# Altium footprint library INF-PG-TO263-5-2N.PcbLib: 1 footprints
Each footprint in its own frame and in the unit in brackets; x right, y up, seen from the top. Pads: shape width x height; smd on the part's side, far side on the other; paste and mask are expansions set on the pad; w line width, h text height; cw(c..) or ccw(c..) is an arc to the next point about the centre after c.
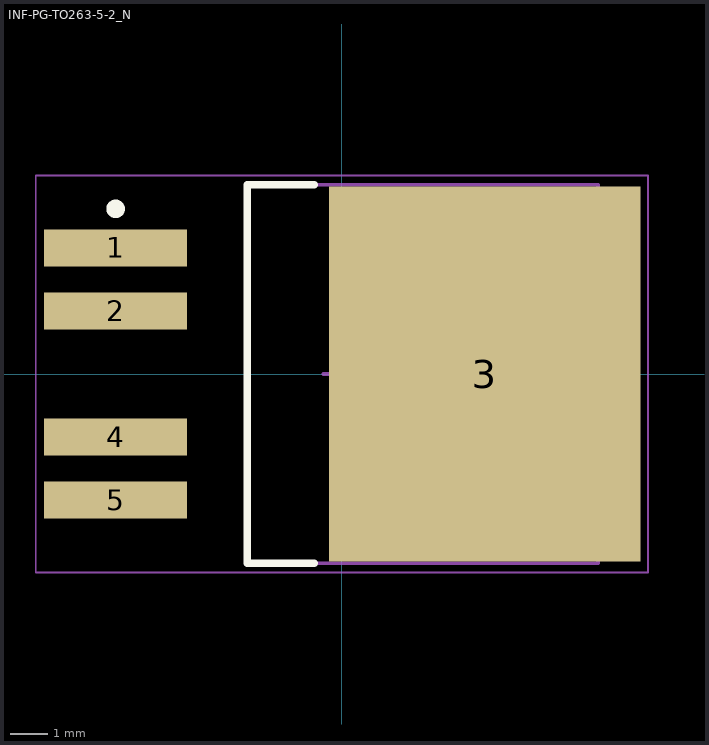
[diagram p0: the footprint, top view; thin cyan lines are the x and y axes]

## INF-PG-TO263-5-2_N [mm] "DPAK, 5-Leads, Body 10x9.25mm, Pitch 1.7mm, IPC Medium Density"
height 4.4
pads (5):
  rect 3.85x1 smd: 1(-6.1,3.4) 2(-6.1,1.7) 4(-6.1,-1.7) 5(-6.1,-3.4)
  rect 8.4x10.1 smd: 3(3.85,0)
Top Overlay:
  circle w0.25: c-6.1,4.45 r0.125
  lines w0.2: -0.75,-5.1 -2.55,-5.1 -2.55,5.1 -0.75,5.1
Mechanical 13:
  lines w0.1: -2.55,-5.1 6.9,-5.1 6.9,5.1 -2.55,5.1 -2.55,-5.1
Mechanical 15:
  lines w0.05: -8.25,-5.35 8.25,-5.35 8.25,5.35 -8.25,5.35 -8.25,-5.35
  lines w0.1: -0.5,0 0.5,0 ; 0,-0.5 0,0.5
3D body: height 4.4, standoff 0.1, extent -2.55,-5.1 6.9,5.1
